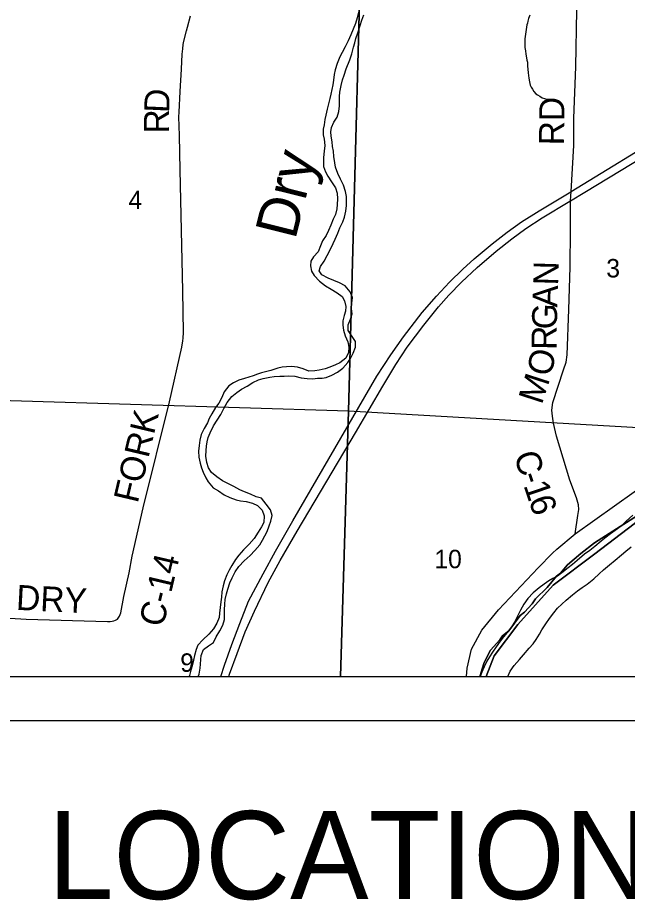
# Model space of a CAD drawing. Extents: x -7.5 to 26.5, y 3.5 to 25.5.
# Drawn here: x -3.099 to -1.714, y 17.091 to 19.097 of the extents above; entities that cross this region are included whole.
import ezdxf

# ---------------------------------------------------------------- set-up
doc = ezdxf.new("R2010")
doc.units = 0
for name, color, linetype in [('GM_X_Corporation', 7, 'Continuous'), ('GM_X_County_Road', 7, 'Continuous'), ('GM_X_County_Road_Text', 7, 'Continuous'), ('GM_X_Interstate_Route', 7, 'Continuous'), ('GM_X_Major_River', 7, 'Continuous'), ('GM_X_Minor_River', 7, 'Continuous'), ('GM_X_Minor_River_Text', 7, 'Continuous'), ('GM_X_Section_Text', 7, 'Continuous'), ('GM_X_State_Route', 7, 'Continuous'), ('SH_Data', 7, 'Continuous'), ('SH_Text', 7, 'Continuous')]:
    doc.layers.add(name, color=color, linetype=linetype)

msp = doc.modelspace()

# ---------------------------------------------------------------- linework, layer by layer
at = {"layer": 'GM_X_Corporation'}
for points in [[(-5.2848, 19.2392), (-5.3003, 18.6476), (-5.3247, 17.7117), (-5.3276, 17.6), (1.4431, 17.6), (1.4431, 24.4)], [(-5.3276, 17.6), (-2.0482, 17.6), (-2.048, 17.6017), (-2.044, 17.6171), (-2.039, 17.6314), (-2.0249, 17.6597), (-2.0038, 17.6826), (-1.9974, 17.6919), (-1.9835, 17.7032), (-1.9575, 17.7384), (-1.9477, 17.746), (-1.9304, 17.7648), (-1.9228, 17.7759), (-1.8958, 17.8019), (-1.8747, 17.8275), (-1.8657, 17.8348), (-1.8499, 17.8532), (-1.8197, 17.8791), (-1.7882, 17.9031), (-1.6488, 17.9921)], [(-1.6488, 17.9921), (-1.7882, 17.9031), (-1.8197, 17.8791), (-1.8499, 17.8532), (-1.8657, 17.8348), (-1.8747, 17.8275), (-1.8958, 17.8019), (-1.9228, 17.7759), (-1.9304, 17.7648), (-1.9477, 17.746), (-1.9575, 17.7384), (-1.9835, 17.7032), (-1.9974, 17.6919), (-2.0038, 17.6826), (-2.0249, 17.6597), (-2.039, 17.6314), (-2.044, 17.6171), (-2.048, 17.6017), (-2.0482, 17.6), (1.4431, 17.6)]]:
    msp.add_lwpolyline(points, dxfattribs=at)
for points in [[(-2.3216, 19.1609), (-2.3477, 18.203), (-3.3388, 18.2326), (-3.3161, 19.1909)], [(-1.3364, 19.1437), (-1.3579, 18.1948), (-1.3746, 18.1766), (-1.4066, 18.1528), (-1.412, 18.1491), (-2.3477, 18.203), (-2.3216, 19.1609)], [(-3.3553, 17.6), (-2.3653, 17.6), (-2.3477, 18.203), (-3.3388, 18.2326)], [(-2.3653, 17.6), (-2.0344, 17.6), (-2.0162, 17.6469), (-1.9628, 17.7181), (-1.8826, 17.8072), (-1.7876, 17.8785), (-1.6985, 17.9468), (-1.6421, 17.9943), (-1.5709, 18.0477), (-1.5545, 18.0223), (-1.5541, 18.0516), (-1.5532, 18.0879), (-1.5251, 18.1005), (-1.5024, 18.1123), (-1.4766, 18.1259), (-1.4567, 18.135), (-1.4372, 18.1422), (-1.412, 18.1491), (-2.3477, 18.203)], [(-2.0344, 17.6), (-1.0391, 17.6), (-1.013, 17.8549), (-1.5575, 17.8988), (-1.5545, 18.0223), (-1.5709, 18.0477), (-1.6421, 17.9943), (-1.6985, 17.9468), (-1.7876, 17.8785), (-1.8826, 17.8072), (-1.9628, 17.7181), (-2.0162, 17.6469)]]:
    msp.add_lwpolyline(points, close=True, dxfattribs=at)
at = {"layer": 'GM_X_County_Road'}
for points in [[(-3.1793, 17.7357), (-3.0798, 17.7302), (-2.8947, 17.7246), (-2.8887, 17.7246), (-2.8842, 17.7251), (-2.8802, 17.7259), (-2.8765, 17.7273), (-2.8725, 17.7299), (-2.8706, 17.732), (-2.8676, 17.7366), (-2.8648, 17.7445), (-2.8575, 17.7812), (-2.846, 17.8356), (-2.8387, 17.8728), (-2.8137, 17.9829), (-2.7542, 18.2235), (-2.7262, 18.3479), (-2.7236, 18.3621), (-2.7228, 18.3689), (-2.7219, 18.3816), (-2.7234, 18.4764), (-2.7299, 18.7512), (-2.7316, 18.8295), (-2.7328, 18.8718), (-2.7324, 18.8822), (-2.73, 18.929), (-2.7267, 18.9801), (-2.7253, 19.014), (-2.724, 19.0264), (-2.7227, 19.0356), (-2.7212, 19.0434), (-2.7156, 19.0668), (-2.7128, 19.0754), (-2.7061, 19.1012)], [(-1.8354, 18.8256), (-1.8357, 18.8688), (-1.8306, 18.985), (-1.8288, 19.1143)], [(-1.8434, 18.6144), (-1.8429, 18.6808), (-1.8416, 18.7017), (-1.8353, 18.8065), (-1.8354, 18.8256)], [(-1.8326, 17.924), (-1.8261, 17.9657), (-1.8243, 17.9788), (-1.8245, 17.9894), (-1.8294, 18.0059), (-1.8449, 18.0461), (-1.8746, 18.146), (-1.8818, 18.1754), (-1.884, 18.1915), (-1.8856, 18.2051), (-1.8833, 18.2226), (-1.8588, 18.2962), (-1.8532, 18.3138), (-1.8508, 18.3303), (-1.8471, 18.4337), (-1.8441, 18.5299), (-1.8434, 18.6144)]]:
    msp.add_lwpolyline(points, dxfattribs=at)
at = {"layer": 'GM_X_Interstate_Route'}
for points in [[(-1.8425, 18.7012), (-1.8416, 18.7017), (-1.6132, 18.841), (-1.5119, 18.9013), (-1.453, 18.9367), (-1.3499, 19.0006), (-1.2112, 19.0844), (-0.9544, 19.2399)], [(-1.8104, 18.7005), (-1.5663, 18.8484), (-1.486, 18.8966), (-1.44, 18.9225), (-1.3365, 18.9774)], [(-2.6371, 17.6), (-2.6291, 17.6254), (-2.6127, 17.6724), (-2.5941, 17.72), (-2.5746, 17.771), (-2.5416, 17.8329), (-2.5133, 17.8846), (-2.4742, 17.9532), (-2.2829, 18.2825), (-2.2515, 18.3304), (-2.2228, 18.3717), (-2.18, 18.4269), (-2.1476, 18.4641), (-2.1178, 18.4958), (-2.088, 18.5252), (-2.0619, 18.549), (-2.021, 18.5829), (-1.9871, 18.6097), (-1.9547, 18.6328), (-1.9144, 18.6578), (-1.8425, 18.7012)], [(-1.8446, 18.6798), (-1.8429, 18.6808), (-1.8104, 18.7005)], [(-2.3318, 18.1537), (-2.2695, 18.2593), (-2.2401, 18.3084), (-2.2138, 18.3479), (-2.176, 18.3983), (-2.1431, 18.4395), (-2.1194, 18.4659), (-2.0909, 18.4957), (-2.055, 18.529), (-2.012, 18.5663), (-1.9764, 18.5944), (-1.9444, 18.6176), (-1.9076, 18.6422), (-1.8446, 18.6798)], [(-2.6194, 17.6), (-2.6178, 17.6052), (-2.6006, 17.6522), (-2.5818, 17.7008), (-2.5612, 17.7478), (-2.5302, 17.813), (-2.5024, 17.8636), (-2.4642, 17.9298), (-2.3318, 18.1537)]]:
    msp.add_lwpolyline(points, dxfattribs=at)
at = {"layer": 'GM_X_Major_River'}
for points in [[(-1.7015, 17.9662), (-1.7167, 17.9526), (-1.7281, 17.9415), (-1.7413, 17.9317), (-1.7525, 17.9237), (-1.7623, 17.9164), (-1.7736, 17.9069), (-1.7876, 17.8951), (-1.7993, 17.886), (-1.811, 17.8773), (-1.8281, 17.863), (-1.8382, 17.8542), (-1.848, 17.8465), (-1.8624, 17.8355), (-1.8729, 17.8279), (-1.8829, 17.8221), (-1.8926, 17.8171), (-1.9027, 17.8098), (-1.9139, 17.8011), (-1.928, 17.7901), (-1.9401, 17.7772), (-1.9493, 17.7638), (-1.9569, 17.7507), (-1.9634, 17.7365), (-1.9691, 17.7253), (-1.9787, 17.71), (-1.9869, 17.7), (-1.9949, 17.6896), (-2.0028, 17.68), (-2.0119, 17.6674), (-2.0206, 17.6547), (-2.0274, 17.6443), (-2.033, 17.6346), (-2.0391, 17.6219), (-2.0448, 17.6091), (-2.0479, 17.6)], [(-1.9856, 17.6), (-1.9798, 17.6117), (-1.9707, 17.6247), (-1.9592, 17.6384), (-1.9498, 17.6487), (-1.9368, 17.6639), (-1.9281, 17.6739), (-1.9214, 17.6835), (-1.9134, 17.6955), (-1.9082, 17.7055), (-1.8994, 17.7197), (-1.891, 17.7316), (-1.8811, 17.7446), (-1.8725, 17.7546), (-1.8631, 17.7642), (-1.8529, 17.773), (-1.8385, 17.785), (-1.8268, 17.7942), (-1.8163, 17.8022), (-1.8054, 17.8098), (-1.7903, 17.8219), (-1.7778, 17.8329), (-1.768, 17.8417), (-1.7544, 17.8531), (-1.7415, 17.8641), (-1.7274, 17.8762), (-1.7173, 17.8846), (-1.7049, 17.8941)]]:
    msp.add_lwpolyline(points, dxfattribs=at)
at = {"layer": 'GM_X_Minor_River'}
for points in [[(-2.3244, 19.1093), (-2.3277, 19.0968), (-2.3315, 19.084), (-2.342, 19.0577), (-2.348, 19.0442), (-2.3548, 19.0303), (-2.3616, 19.018), (-2.3668, 19.0079), (-2.3732, 18.9929), (-2.3777, 18.9786), (-2.3799, 18.968), (-2.3814, 18.9547), (-2.3832, 18.9445), (-2.385, 18.934), (-2.3875, 18.923), (-2.3897, 18.9132), (-2.393, 18.9008)], [(-2.3733, 18.8707), (-2.3696, 18.8839), (-2.3681, 18.8963), (-2.3678, 18.9073), (-2.3679, 18.9176), (-2.3669, 18.9278), (-2.3643, 18.9429), (-2.3609, 18.9554), (-2.3576, 18.9663), (-2.3527, 18.9806), (-2.3446, 19.0009), (-2.3397, 19.0144), (-2.3359, 19.0295), (-2.333, 19.0396), (-2.3308, 19.0495), (-2.3255, 19.0649), (-2.3206, 19.0792), (-2.3172, 19.0916), (-2.3128, 19.1036)], [(-1.9356, 19.1023), (-1.9381, 19.0948), (-1.9399, 19.0888), (-1.9408, 19.0846), (-1.9421, 19.0805), (-1.943, 19.0756), (-1.9439, 19.0703), (-1.9445, 19.0646), (-1.9451, 19.0593), (-1.946, 19.054), (-1.9466, 19.0487), (-1.9469, 19.0384), (-1.9465, 19.0289), (-1.9456, 19.0217), (-1.9444, 19.014), (-1.9427, 19.006), (-1.9422, 19.0003), (-1.9408, 18.9961), (-1.9404, 18.9869), (-1.9398, 18.9801), (-1.939, 18.9713), (-1.9375, 18.9591), (-1.9363, 18.9514), (-1.9346, 18.9438), (-1.9325, 18.9388), (-1.9297, 18.9341), (-1.9264, 18.929), (-1.922, 18.924), (-1.918, 18.9212), (-1.9127, 18.9183), (-1.9072, 18.9151)], [(-2.393, 18.9008), (-2.396, 18.8891), (-2.399, 18.8755), (-2.4011, 18.8657), (-2.4029, 18.8536), (-2.4047, 18.8434), (-2.4047, 18.8305), (-2.4026, 18.8209), (-2.4015, 18.8065), (-2.4026, 18.7932), (-2.4041, 18.7789), (-2.4044, 18.7686), (-2.4039, 18.7584), (-2.4, 18.7469), (-2.3946, 18.7365), (-2.3858, 18.7241), (-2.3771, 18.7102), (-2.3728, 18.6984), (-2.3724, 18.6855), (-2.3731, 18.6722), (-2.3738, 18.6623), (-2.3771, 18.6499), (-2.3819, 18.639), (-2.3876, 18.6251), (-2.3928, 18.6131), (-2.398, 18.6022), (-2.4063, 18.5896), (-2.4112, 18.5787), (-2.4161, 18.5644), (-2.427, 18.5533), (-2.4329, 18.5432), (-2.4335, 18.5333), (-2.4316, 18.5211), (-2.4254, 18.5111), (-2.4132, 18.4979), (-2.3999, 18.4873), (-2.3868, 18.4798), (-2.3734, 18.4714), (-2.3618, 18.4636), (-2.3568, 18.4536), (-2.3537, 18.4406), (-2.3544, 18.4296), (-2.3576, 18.4198), (-2.3599, 18.4077), (-2.3601, 18.3983), (-2.3589, 18.3865), (-2.355, 18.3735), (-2.349, 18.36), (-2.347, 18.3482), (-2.3477, 18.3357), (-2.3537, 18.323), (-2.3672, 18.3127), (-2.3768, 18.3076), (-2.3898, 18.303), (-2.4005, 18.2991), (-2.4139, 18.2957), (-2.4238, 18.294), (-2.4374, 18.2932), (-2.4502, 18.2985), (-2.4633, 18.3026), (-2.4769, 18.3041), (-2.4883, 18.3036), (-2.4978, 18.3024), (-2.5077, 18.3), (-2.5238, 18.2954), (-2.5333, 18.2927), (-2.5448, 18.2895), (-2.5543, 18.2867), (-2.5643, 18.2832), (-2.5738, 18.28), (-2.5834, 18.2772), (-2.5964, 18.273), (-2.609, 18.2673), (-2.6194, 18.26), (-2.6296, 18.2469), (-2.6353, 18.2334), (-2.642, 18.2211), (-2.6499, 18.211), (-2.6578, 18.1964), (-2.6638, 18.1856), (-2.6678, 18.1758), (-2.675, 18.1631), (-2.6825, 18.1493), (-2.6855, 18.1364), (-2.6869, 18.1243), (-2.6884, 18.1119), (-2.6876, 18.0978), (-2.6846, 18.0844), (-2.6814, 18.0741), (-2.6775, 18.0641), (-2.6714, 18.0515), (-2.6663, 18.0419), (-2.6549, 18.0287), (-2.6426, 18.0215), (-2.6299, 18.0128), (-2.6168, 18.0068), (-2.6029, 18.0015), (-2.5931, 17.999), (-2.5799, 17.9971), (-2.5652, 17.9937), (-2.5544, 17.9885)], [(-1.9072, 18.9151), (-1.9019, 18.913), (-1.897, 18.9117), (-1.8921, 18.9115), (-1.8841, 18.9116), (-1.8792, 18.9111), (-1.8732, 18.9097), (-1.869, 18.9084)], [(-2.5428, 17.9093), (-2.5376, 17.919), (-2.5324, 17.9291), (-2.5275, 17.9423), (-2.5239, 17.9524), (-2.5205, 17.9653), (-2.5243, 17.9786), (-2.5342, 17.9914), (-2.5453, 18.005), (-2.5573, 18.0076), (-2.57, 18.014), (-2.5839, 18.0196), (-2.594, 18.0241), (-2.6082, 18.0313), (-2.6217, 18.038), (-2.6333, 18.044), (-2.6467, 18.0535), (-2.6586, 18.0633), (-2.6651, 18.0737), (-2.6693, 18.0863), (-2.6713, 18.1), (-2.6709, 18.1129), (-2.6703, 18.1228), (-2.6685, 18.133), (-2.6664, 18.1428), (-2.6619, 18.1537), (-2.654, 18.169), (-2.6457, 18.1825), (-2.6374, 18.1948), (-2.6306, 18.2086), (-2.6234, 18.2225), (-2.6128, 18.2359), (-2.6008, 18.2454), (-2.5908, 18.2524), (-2.5778, 18.2593), (-2.565, 18.2677), (-2.5516, 18.2742), (-2.5413, 18.2769), (-2.5261, 18.2799), (-2.5166, 18.2812), (-2.5033, 18.2824), (-2.4934, 18.2821), (-2.4836, 18.2827), (-2.4696, 18.2823), (-2.4549, 18.2785), (-2.4413, 18.2766), (-2.4288, 18.2763), (-2.4181, 18.2776), (-2.4075, 18.2777), (-2.398, 18.2793), (-2.385, 18.2843), (-2.3727, 18.2912), (-2.36, 18.3007), (-2.3486, 18.313), (-2.3419, 18.3242), (-2.3367, 18.3347), (-2.3318, 18.3478), (-2.3315, 18.3607), (-2.3483, 18.3862), (-2.3483, 18.3991), (-2.3431, 18.4119), (-2.339, 18.4239), (-2.3409, 18.4361), (-2.3399, 18.4482), (-2.338, 18.4611), (-2.3434, 18.4741), (-2.3552, 18.4873), (-2.3682, 18.4945), (-2.3806, 18.4993), (-2.3933, 18.505), (-2.4079, 18.5122), (-2.4138, 18.5218), (-2.4109, 18.5316), (-2.4026, 18.5432), (-2.3958, 18.5563), (-2.3883, 18.5705), (-2.3819, 18.5836), (-2.3774, 18.5934), (-2.3718, 18.6069), (-2.3669, 18.6193), (-2.3601, 18.6331), (-2.3568, 18.6437), (-2.3534, 18.6569), (-2.352, 18.6701), (-2.3517, 18.6796), (-2.3522, 18.6906), (-2.3542, 18.7017), (-2.3587, 18.7162), (-2.3652, 18.73), (-2.3717, 18.7427), (-2.3766, 18.7569), (-2.3786, 18.7672), (-2.3806, 18.7813), (-2.3818, 18.7935), (-2.3834, 18.8045), (-2.3846, 18.8144), (-2.3866, 18.8277), (-2.3874, 18.8373), (-2.386, 18.8475), (-2.3804, 18.8591), (-2.3733, 18.8707)], [(-2.5544, 17.9885), (-2.5437, 17.978), (-2.5391, 17.965), (-2.5395, 17.9498), (-2.545, 17.9397), (-2.5525, 17.9274), (-2.562, 17.9132), (-2.5733, 17.9006), (-2.5858, 17.8876), (-2.5963, 17.8754), (-2.6038, 17.8653), (-2.6125, 17.8519), (-2.6188, 17.8414), (-2.6236, 17.8309), (-2.6289, 17.8167), (-2.6318, 17.8057), (-2.6348, 17.7918), (-2.6363, 17.7797), (-2.6377, 17.7695), (-2.6391, 17.7562), (-2.6406, 17.7438), (-2.6416, 17.7339), (-2.6465, 17.7211), (-2.6544, 17.7081), (-2.6646, 17.6958), (-2.6785, 17.6833), (-2.6895, 17.6707), (-2.6935, 17.6609), (-2.6969, 17.6473), (-2.6994, 17.6368), (-2.7028, 17.6236), (-2.7057, 17.6138), (-2.7086, 17.6017), (-2.7093, 17.6)], [(-2.6888, 17.6), (-2.6866, 17.6053), (-2.6844, 17.6182), (-2.6837, 17.6276), (-2.6831, 17.6379), (-2.6825, 17.6477), (-2.6772, 17.6612), (-2.6652, 17.6693), (-2.6541, 17.6766), (-2.6477, 17.6901), (-2.6397, 17.7031), (-2.633, 17.7166), (-2.6292, 17.7294), (-2.629, 17.7389), (-2.6294, 17.7511), (-2.6287, 17.7639), (-2.6273, 17.7745), (-2.6247, 17.7877), (-2.6218, 17.7979), (-2.6172, 17.8126), (-2.612, 17.8242), (-2.6045, 17.8373), (-2.5962, 17.8496), (-2.5845, 17.8622), (-2.5706, 17.8744), (-2.56, 17.8862), (-2.5487, 17.8992), (-2.5428, 17.9093)]]:
    msp.add_lwpolyline(points, dxfattribs=at)
at = {"layer": 'GM_X_State_Route'}
for points in [[(-1.8326, 17.924), (-1.6536, 18.0511)], [(-2.0792, 17.6), (-2.0775, 17.6182), (-2.068, 17.6619), (-2.0448, 17.7052), (-2.0064, 17.7515), (-1.9167, 17.8467), (-1.8836, 17.8798), (-1.8742, 17.8891), (-1.8326, 17.924)]]:
    msp.add_lwpolyline(points, dxfattribs=at)
at = {"layer": 'SH_Data'}
for p, q in [((-5.3569, 17.6), (1.4431, 17.6)), ((-5.4569, 17.5), (1.5431, 17.5))]:
    msp.add_line(p, q, dxfattribs=at)

# ---------------------------------------------------------------- texts
at = {"layer": 'GM_X_County_Road_Text'}
for s, height, rotation, p in [('D', 0.0568, 87.4778, (-2.7552, 18.8796)), ('RD', 0.05682, 89.5103, (-1.8578, 18.8067)), ('R', 0.0568, 90.2819, (-2.755, 18.834)), ('N', 0.0568, 88.2784, (-1.8713, 18.4879)), ('A', 0.0568, 88.2787, (-1.8728, 18.4379)), ('G', 0.0568, 88.2786, (-1.8743, 18.3879)), ('R', 0.0568, 89.299, (-1.8749, 18.3416)), ('O', 0.0568, 76.6038, (-1.8881, 18.2793)), ('M', 0.0568, 72.0746, (-1.9084, 18.2159)), ('FORK', 0.05682, 76.7151, (-2.8264, 17.9916)), ('C', 0.0568, 286.6483, (-1.972, 18.1033)), ('-', 0.0568, 288.8678, (-1.9579, 18.0563)), ('1', 0.0568, 288.868, (-1.9503, 18.0342)), ('6', 0.0568, 288.9111, (-1.939, 18.001)), ('C-14', 0.05682, 76.7988, (-2.7686, 17.7098)), ('DRY', 0.05682, 357.073, (-3.1035, 17.7513))]:
    msp.add_text(s, height=height, rotation=rotation, dxfattribs=at).set_placement(p)
at = {"layer": 'GM_X_Minor_River_Text'}
msp.add_text('Dry', height=0.0947, rotation=75.9368, dxfattribs=at).set_placement((-2.4685, 18.5902))
at = {"layer": 'GM_X_Section_Text'}
for s, height, p in [('4', 0.0419, (-2.8472, 18.6619)), ('3', 0.0419, (-1.7617, 18.5066)), ('10', 0.04186, (-2.1522, 17.8457)), ('9', 0.0419, (-2.7297, 17.6103))]:
    msp.add_text(s, height=height, rotation=0, dxfattribs=at).set_placement(p)
at = {"layer": 'SH_Text'}
msp.add_text('LOCATION MAP', height=0.2, dxfattribs=at).set_placement((-3.03, 17.0938))

doc.saveas('drawing.dxf')
